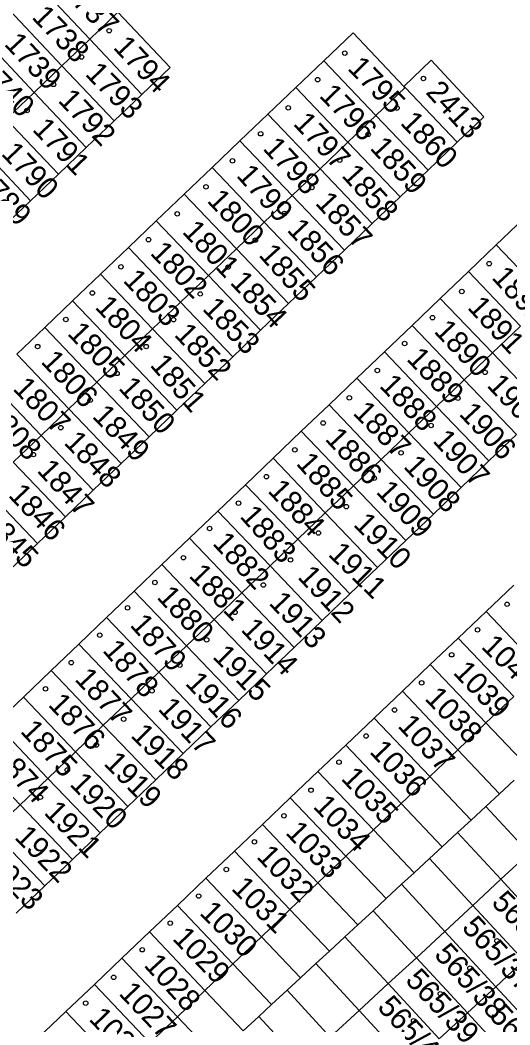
# Model space of a CAD drawing. Extents: x -735249 to -729401, y -1124843 to -1121828.
# Drawn here: x -733357.4 to -733319, y -1123266.5 to -1123187.9 of the extents above; entities that cross this region are included whole.
import ezdxf

# ---------------------------------------------------------------- set-up
doc = ezdxf.new("R2010")
doc.units = 0
for name, color, linetype in [('Vrstva 1', 7, 'Continuous'), ('Vrstva 19', 7, 'Continuous'), ('Vrstva 25', 7, 'Continuous'), ('Vrstva 4', 7, 'Continuous')]:
    doc.layers.add(name, color=color, linetype=linetype)

msp = doc.modelspace()

# ---------------------------------------------------------------- linework, layer by layer
at = {"layer": 'Vrstva 1'}
for points in [[(-733355.97, -1123185.04), (-733351.91, -1123189.36)], [(-733358.16, -1123187.12), (-733354.09, -1123191.44)], [(-733351.91, -1123189.36), (-733349.7, -1123187.25)], [(-733345.62, -1123191.57), (-733349.7, -1123187.25)], [(-733360.34, -1123189.21), (-733356.27, -1123193.53)], [(-733354.09, -1123191.44), (-733351.91, -1123189.36)], [(-733351.91, -1123189.36), (-733347.83, -1123193.68)], [(-733333.59, -1123191.06), (-733331.3, -1123188.87)], [(-733331.3, -1123188.87), (-733327.31, -1123193.05)], [(-733335.78, -1123193.15), (-733333.59, -1123191.06)], [(-733333.59, -1123191.06), (-733329.51, -1123195.34)], [(-733327.31, -1123193.05), (-733325.18, -1123191.01)], [(-733325.18, -1123191.01), (-733321.06, -1123195.43)], [(-733356.27, -1123193.53), (-733354.09, -1123191.44)], [(-733354.09, -1123191.44), (-733350.01, -1123195.76)], [(-733347.83, -1123193.68), (-733345.62, -1123191.57)], [(-733337.96, -1123195.23), (-733335.78, -1123193.15)], [(-733335.78, -1123193.15), (-733331.7, -1123197.43)], [(-733329.51, -1123195.34), (-733327.22, -1123193.15)], [(-733327.31, -1123193.05), (-733327.22, -1123193.15)], [(-733327.22, -1123193.15), (-733323.14, -1123197.42)], [(-733358.45, -1123195.61), (-733356.27, -1123193.53)], [(-733356.27, -1123193.53), (-733352.19, -1123197.84)], [(-733350.01, -1123195.76), (-733347.83, -1123193.68)], [(-733358.45, -1123195.61), (-733354.37, -1123199.92)], [(-733352.19, -1123197.84), (-733350.01, -1123195.76)], [(-733340.15, -1123197.32), (-733337.96, -1123195.23)], [(-733337.96, -1123195.23), (-733333.88, -1123199.51)], [(-733331.7, -1123197.43), (-733329.51, -1123195.34)], [(-733329.51, -1123195.34), (-733325.43, -1123199.61)], [(-733321.06, -1123195.43), (-733323.14, -1123197.42)], [(-733342.33, -1123199.4), (-733340.15, -1123197.32)], [(-733340.15, -1123197.32), (-733336.07, -1123201.6)], [(-733333.88, -1123199.51), (-733331.7, -1123197.43)], [(-733331.7, -1123197.43), (-733327.62, -1123201.7)], [(-733325.43, -1123199.61), (-733323.14, -1123197.42)], [(-733360.62, -1123197.69), (-733356.54, -1123202)], [(-733354.37, -1123199.92), (-733352.19, -1123197.84)], [(-733344.51, -1123201.49), (-733342.33, -1123199.4)], [(-733342.33, -1123199.4), (-733338.25, -1123203.68)], [(-733336.07, -1123201.6), (-733333.88, -1123199.51)], [(-733333.88, -1123199.51), (-733329.8, -1123203.78)], [(-733327.62, -1123201.7), (-733325.43, -1123199.61)], [(-733356.54, -1123202), (-733354.37, -1123199.92)], [(-733358.73, -1123204.09), (-733356.54, -1123202)], [(-733346.7, -1123203.57), (-733344.51, -1123201.49)], [(-733344.51, -1123201.49), (-733340.43, -1123205.77)], [(-733338.25, -1123203.68), (-733336.07, -1123201.6)], [(-733336.07, -1123201.6), (-733331.98, -1123205.87)], [(-733329.8, -1123203.78), (-733327.62, -1123201.7)], [(-733348.88, -1123205.66), (-733346.7, -1123203.57)], [(-733346.7, -1123203.57), (-733342.62, -1123207.85)], [(-733340.43, -1123205.77), (-733338.25, -1123203.68)], [(-733338.25, -1123203.68), (-733334.17, -1123207.95)], [(-733320.09, -1123205.46), (-733317.93, -1123203.39)], [(-733331.98, -1123205.87), (-733329.8, -1123203.78)], [(-733351.07, -1123207.75), (-733348.88, -1123205.66)], [(-733348.88, -1123205.66), (-733344.8, -1123209.94)], [(-733342.62, -1123207.85), (-733340.43, -1123205.77)], [(-733340.43, -1123205.77), (-733336.35, -1123210.04)], [(-733334.17, -1123207.95), (-733331.98, -1123205.87)], [(-733322.26, -1123207.53), (-733320.09, -1123205.46)], [(-733320.09, -1123205.46), (-733316.01, -1123209.73)], [(-733324.47, -1123209.64), (-733322.26, -1123207.53)], [(-733322.26, -1123207.53), (-733318.18, -1123211.8)], [(-733353.25, -1123209.83), (-733351.07, -1123207.75)], [(-733351.07, -1123207.75), (-733346.99, -1123212.03)], [(-733344.8, -1123209.94), (-733342.62, -1123207.85)], [(-733342.62, -1123207.85), (-733338.54, -1123212.13)], [(-733336.35, -1123210.04), (-733334.17, -1123207.95)], [(-733355.44, -1123211.92), (-733353.25, -1123209.83)], [(-733353.25, -1123209.83), (-733349.17, -1123214.11)], [(-733346.99, -1123212.03), (-733344.8, -1123209.94)], [(-733344.8, -1123209.94), (-733340.72, -1123214.21)], [(-733326.67, -1123211.75), (-733324.47, -1123209.64)], [(-733324.47, -1123209.64), (-733320.38, -1123213.91)], [(-733338.54, -1123212.13), (-733336.35, -1123210.04)], [(-733357.62, -1123214), (-733355.44, -1123211.92)], [(-733355.44, -1123211.92), (-733351.36, -1123216.2)], [(-733349.17, -1123214.11), (-733346.99, -1123212.03)], [(-733346.99, -1123212.03), (-733342.9, -1123216.3)], [(-733340.72, -1123214.21), (-733338.54, -1123212.13)], [(-733328.84, -1123213.82), (-733326.67, -1123211.75)], [(-733326.67, -1123211.75), (-733322.59, -1123216.02)], [(-733320.38, -1123213.91), (-733318.18, -1123211.8)], [(-733331.01, -1123215.89), (-733328.84, -1123213.82)], [(-733328.84, -1123213.82), (-733324.76, -1123218.09)], [(-733322.59, -1123216.02), (-733320.38, -1123213.91)], [(-733320.38, -1123213.91), (-733316.3, -1123218.18)], [(-733357.62, -1123214), (-733353.54, -1123218.28)], [(-733351.36, -1123216.2), (-733349.17, -1123214.11)], [(-733349.17, -1123214.11), (-733345.09, -1123218.38)], [(-733342.9, -1123216.3), (-733340.72, -1123214.21)], [(-733359.8, -1123216.09), (-733355.72, -1123220.37)], [(-733353.54, -1123218.28), (-733351.36, -1123216.2)], [(-733351.36, -1123216.2), (-733347.27, -1123220.47)], [(-733345.09, -1123218.38), (-733342.9, -1123216.3)], [(-733333.18, -1123217.96), (-733331.01, -1123215.89)], [(-733331.01, -1123215.89), (-733326.92, -1123220.17)], [(-733324.76, -1123218.09), (-733322.59, -1123216.02)], [(-733322.59, -1123216.02), (-733318.5, -1123220.29)], [(-733355.72, -1123220.37), (-733353.54, -1123218.28)], [(-733353.54, -1123218.28), (-733349.46, -1123222.56)], [(-733347.27, -1123220.47), (-733345.09, -1123218.38)], [(-733335.35, -1123220.04), (-733333.18, -1123217.96)], [(-733333.18, -1123217.96), (-733329.09, -1123222.24)], [(-733326.92, -1123220.17), (-733324.76, -1123218.09)], [(-733324.76, -1123218.09), (-733320.67, -1123222.36)], [(-733337.55, -1123222.14), (-733335.35, -1123220.04)], [(-733335.35, -1123220.04), (-733331.26, -1123224.31)], [(-733329.09, -1123222.24), (-733326.92, -1123220.17)], [(-733326.92, -1123220.17), (-733322.84, -1123224.43)], [(-733357.91, -1123222.45), (-733355.72, -1123220.37)], [(-733355.72, -1123220.37), (-733351.64, -1123224.64)], [(-733349.46, -1123222.56), (-733347.27, -1123220.47)], [(-733320.67, -1123222.36), (-733318.5, -1123220.29)], [(-733357.91, -1123222.45), (-733353.82, -1123226.73)], [(-733351.64, -1123224.64), (-733349.46, -1123222.56)], [(-733339.72, -1123224.22), (-733337.55, -1123222.14)], [(-733337.55, -1123222.14), (-733333.47, -1123226.42)], [(-733331.26, -1123224.31), (-733329.09, -1123222.24)], [(-733329.09, -1123222.24), (-733325, -1123226.51)], [(-733322.84, -1123224.43), (-733320.67, -1123222.36)], [(-733360.09, -1123224.54), (-733356.01, -1123228.81)], [(-733353.82, -1123226.73), (-733351.64, -1123224.64)], [(-733341.89, -1123226.29), (-733339.72, -1123224.22)], [(-733339.72, -1123224.22), (-733335.63, -1123228.49)], [(-733333.47, -1123226.42), (-733331.26, -1123224.31)], [(-733331.26, -1123224.31), (-733327.17, -1123228.58)], [(-733325, -1123226.51), (-733322.84, -1123224.43)], [(-733344.1, -1123228.4), (-733341.89, -1123226.29)], [(-733341.89, -1123226.29), (-733337.8, -1123230.57)], [(-733335.63, -1123228.49), (-733333.47, -1123226.42)], [(-733333.47, -1123226.42), (-733329.38, -1123230.69)], [(-733327.17, -1123228.58), (-733325, -1123226.51)], [(-733356.01, -1123228.81), (-733353.82, -1123226.73)], [(-733358.19, -1123230.9), (-733356.01, -1123228.81)], [(-733346.26, -1123230.47), (-733344.1, -1123228.4)], [(-733344.1, -1123228.4), (-733340.01, -1123232.67)], [(-733337.8, -1123230.57), (-733335.63, -1123228.49)], [(-733335.63, -1123228.49), (-733331.54, -1123232.76)], [(-733329.38, -1123230.69), (-733327.17, -1123228.58)], [(-733348.43, -1123232.54), (-733346.26, -1123230.47)], [(-733346.26, -1123230.47), (-733342.18, -1123234.75)], [(-733340.01, -1123232.67), (-733337.8, -1123230.57)], [(-733337.8, -1123230.57), (-733333.71, -1123234.84)], [(-733331.54, -1123232.76), (-733329.38, -1123230.69)], [(-733350.6, -1123234.61), (-733348.43, -1123232.54)], [(-733348.43, -1123232.54), (-733344.34, -1123236.82)], [(-733342.18, -1123234.75), (-733340.01, -1123232.67)], [(-733340.01, -1123232.67), (-733335.92, -1123236.95)], [(-733333.71, -1123234.84), (-733331.54, -1123232.76)], [(-733320.89, -1123234.14), (-733318.72, -1123232.07)], [(-733323.07, -1123236.21), (-733320.89, -1123234.14)], [(-733320.89, -1123234.14), (-733316.55, -1123238.71)], [(-733352.77, -1123236.69), (-733350.6, -1123234.61)], [(-733350.6, -1123234.61), (-733346.51, -1123238.89)], [(-733344.34, -1123236.82), (-733342.18, -1123234.75)], [(-733342.18, -1123234.75), (-733338.08, -1123239.02)], [(-733335.92, -1123236.95), (-733333.71, -1123234.84)], [(-733354.94, -1123238.76), (-733352.77, -1123236.69)], [(-733352.77, -1123236.69), (-733348.68, -1123240.97)], [(-733325.25, -1123238.28), (-733323.07, -1123236.21)], [(-733323.07, -1123236.21), (-733318.72, -1123240.78)], [(-733346.51, -1123238.89), (-733344.34, -1123236.82)], [(-733344.34, -1123236.82), (-733340.25, -1123241.09)], [(-733338.08, -1123239.02), (-733335.92, -1123236.95)], [(-733327.44, -1123240.37), (-733325.25, -1123238.28)], [(-733325.25, -1123238.28), (-733320.9, -1123242.85)], [(-733357.11, -1123240.83), (-733354.94, -1123238.76)], [(-733354.94, -1123238.76), (-733350.85, -1123243.04)], [(-733348.68, -1123240.97), (-733346.51, -1123238.89)], [(-733346.51, -1123238.89), (-733342.42, -1123243.17)], [(-733340.25, -1123241.09), (-733338.08, -1123239.02)], [(-733329.65, -1123242.47), (-733327.44, -1123240.37)], [(-733327.44, -1123240.37), (-733323.1, -1123244.95)], [(-733359.28, -1123242.91), (-733357.11, -1123240.83)], [(-733357.11, -1123240.83), (-733353.02, -1123245.11)], [(-733350.85, -1123243.04), (-733348.68, -1123240.97)], [(-733348.68, -1123240.97), (-733344.59, -1123245.24)], [(-733342.42, -1123243.17), (-733340.25, -1123241.09)], [(-733359.28, -1123242.91), (-733355.18, -1123247.19)], [(-733331.87, -1123244.59), (-733329.65, -1123242.47)], [(-733329.65, -1123242.47), (-733325.3, -1123247.04)], [(-733320.9, -1123242.85), (-733317.6, -1123246.32)], [(-733353.02, -1123245.11), (-733350.85, -1123243.04)], [(-733350.85, -1123243.04), (-733346.75, -1123247.31)], [(-733344.59, -1123245.24), (-733342.42, -1123243.17)], [(-733334.05, -1123246.66), (-733331.87, -1123244.59)], [(-733331.87, -1123244.59), (-733327.53, -1123249.16)], [(-733361.45, -1123244.98), (-733357.35, -1123249.26)], [(-733355.18, -1123247.19), (-733353.02, -1123245.11)], [(-733353.02, -1123245.11), (-733348.92, -1123249.39)], [(-733346.75, -1123247.31), (-733344.59, -1123245.24)], [(-733323.1, -1123244.95), (-733319.84, -1123248.39)], [(-733336.21, -1123248.71), (-733334.05, -1123246.66)], [(-733334.05, -1123246.66), (-733329.7, -1123251.23)], [(-733357.35, -1123249.26), (-733355.18, -1123247.19)], [(-733355.18, -1123247.19), (-733351.09, -1123251.46)], [(-733348.92, -1123249.39), (-733346.75, -1123247.31)], [(-733325.3, -1123247.04), (-733322.06, -1123250.45)], [(-733319.84, -1123248.39), (-733318.69, -1123247.33)], [(-733320.91, -1123249.38), (-733319.84, -1123248.39)], [(-733359.52, -1123251.33), (-733357.35, -1123249.26)], [(-733357.35, -1123249.26), (-733353.26, -1123253.54)], [(-733338.4, -1123250.8), (-733336.21, -1123248.71)], [(-733336.21, -1123248.71), (-733331.86, -1123253.29)], [(-733327.53, -1123249.16), (-733324.32, -1123252.54)], [(-733351.09, -1123251.46), (-733348.92, -1123249.39)], [(-733322.06, -1123250.45), (-733320.91, -1123249.38)], [(-733317.51, -1123253.05), (-733320.91, -1123249.38)], [(-733340.59, -1123252.89), (-733338.4, -1123250.8)], [(-733338.4, -1123250.8), (-733334.05, -1123255.37)], [(-733323.11, -1123251.42), (-733322.06, -1123250.45)], [(-733359.52, -1123251.33), (-733355.43, -1123255.61)], [(-733353.26, -1123253.54), (-733351.09, -1123251.46)], [(-733329.7, -1123251.23), (-733326.52, -1123254.57)], [(-733324.32, -1123252.54), (-733323.11, -1123251.42)], [(-733319.72, -1123255.09), (-733323.11, -1123251.42)], [(-733342.82, -1123255.01), (-733340.59, -1123252.89)], [(-733340.59, -1123252.89), (-733336.24, -1123257.46)], [(-733325.31, -1123253.46), (-733324.32, -1123252.54)], [(-733355.43, -1123255.61), (-733353.26, -1123253.54)], [(-733331.86, -1123253.29), (-733328.71, -1123256.6)], [(-733326.52, -1123254.57), (-733325.31, -1123253.46)], [(-733321.92, -1123257.13), (-733325.31, -1123253.46)], [(-733327.51, -1123255.48), (-733326.52, -1123254.57)], [(-733345.05, -1123257.13), (-733342.82, -1123255.01)], [(-733342.82, -1123255.01), (-733338.47, -1123259.58)], [(-733334.05, -1123255.37), (-733330.93, -1123258.65)], [(-733328.71, -1123256.6), (-733327.51, -1123255.48)], [(-733324.12, -1123259.16), (-733327.51, -1123255.48)], [(-733319.72, -1123255.09), (-733315.73, -1123259.42)], [(-733357.67, -1123257.75), (-733355.43, -1123255.61)], [(-733347.24, -1123259.21), (-733345.05, -1123257.13)], [(-733345.05, -1123257.13), (-733340.7, -1123261.7)], [(-733329.73, -1123257.55), (-733328.71, -1123256.6)], [(-733321.92, -1123257.13), (-733317.93, -1123261.45)], [(-733336.24, -1123257.46), (-733333.15, -1123260.71)], [(-733330.93, -1123258.65), (-733329.73, -1123257.55)], [(-733326.34, -1123261.22), (-733329.73, -1123257.55)], [(-733331.93, -1123259.58), (-733330.93, -1123258.65)], [(-733349.39, -1123261.26), (-733347.24, -1123259.21)], [(-733347.24, -1123259.21), (-733342.89, -1123263.79)], [(-733324.12, -1123259.16), (-733320.13, -1123263.49)], [(-733338.47, -1123259.58), (-733335.41, -1123262.79)], [(-733333.15, -1123260.71), (-733331.93, -1123259.58)], [(-733328.54, -1123263.25), (-733331.93, -1123259.58)], [(-733334.2, -1123261.67), (-733333.15, -1123260.71)], [(-733351.55, -1123263.32), (-733349.39, -1123261.26)], [(-733349.39, -1123261.26), (-733345.04, -1123265.84)], [(-733340.7, -1123261.7), (-733337.67, -1123264.88)], [(-733335.41, -1123262.79), (-733334.2, -1123261.67)], [(-733330.81, -1123265.35), (-733334.2, -1123261.67)], [(-733326.34, -1123261.22), (-733322.35, -1123265.54)], [(-733320.13, -1123263.49), (-733317.93, -1123261.45)], [(-733353.78, -1123265.44), (-733351.55, -1123263.32)], [(-733351.55, -1123263.32), (-733347.2, -1123267.89)], [(-733336.46, -1123263.77), (-733335.41, -1123262.79)], [(-733328.54, -1123263.25), (-733324.55, -1123267.57)], [(-733342.89, -1123263.79), (-733339.9, -1123266.94)], [(-733337.67, -1123264.88), (-733336.46, -1123263.77)], [(-733333.08, -1123267.45), (-733336.46, -1123263.77)], [(-733322.35, -1123265.54), (-733320.13, -1123263.49)], [(-733320.13, -1123263.49), (-733316.13, -1123267.81)], [(-733338.67, -1123265.81), (-733337.67, -1123264.88)], [(-733356, -1123267.55), (-733353.78, -1123265.44)], [(-733353.78, -1123265.44), (-733349.43, -1123270.02)], [(-733339.9, -1123266.94), (-733338.67, -1123265.81)], [(-733335.28, -1123269.49), (-733338.67, -1123265.81)], [(-733330.81, -1123265.35), (-733326.82, -1123269.68)], [(-733324.55, -1123267.57), (-733322.35, -1123265.54)], [(-733322.35, -1123265.54), (-733318.35, -1123269.87)], [(-733345.04, -1123265.84), (-733342.08, -1123268.96)]]:
    msp.add_lwpolyline(points, dxfattribs=at)
at = {"layer": 'Vrstva 25'}
for centre in [(-733350.39, -1123188.7), (-733331.95, -1123190.45), (-733352.55, -1123190.75), (-733334.07, -1123192.53), (-733325.79, -1123192.44), (-733354.75, -1123192.9), (-733356.82, -1123194.94), (-733336.37, -1123194.73), (-733327.86, -1123194.74), (-733338.53, -1123196.76), (-733330.11, -1123196.81), (-733340.74, -1123198.88), (-733332.34, -1123198.83), (-733342.81, -1123200.91), (-733334.52, -1123200.97), (-733345.06, -1123203.03), (-733336.66, -1123203), (-733347.31, -1123205.05), (-733338.95, -1123205.09), (-733320.64, -1123206.92), (-733349.47, -1123207.17), (-733341.08, -1123207.19), (-733351.71, -1123209.22), (-733343.26, -1123209.29), (-733322.78, -1123209.1), (-733353.78, -1123211.29), (-733345.35, -1123211.31), (-733325.08, -1123211.15), (-733327.26, -1123213.17), (-733355.99, -1123213.41), (-733347.49, -1123213.41), (-733349.78, -1123215.51), (-733329.4, -1123215.28), (-733320.96, -1123215.43), (-733351.88, -1123217.61), (-733331.59, -1123217.42), (-733323.09, -1123217.45), (-733333.64, -1123219.39), (-733325.19, -1123219.58), (-733354.18, -1123219.75), (-733356.32, -1123221.86), (-733335.86, -1123221.49), (-733327.54, -1123221.72), (-733338.08, -1123223.59), (-733329.64, -1123223.71), (-733340.27, -1123225.66), (-733331.82, -1123225.93), (-733342.53, -1123227.64), (-733334.01, -1123227.99), (-733344.58, -1123229.93), (-733336.19, -1123230.1), (-733346.81, -1123231.87), (-733338.32, -1123232.06), (-733319.24, -1123233.57), (-733348.95, -1123233.85), (-733340.54, -1123234.2), (-733351.13, -1123235.99), (-733321.55, -1123235.57), (-733342.76, -1123236.35), (-733323.58, -1123237.52), (-733353.36, -1123238.14), (-733344.86, -1123238.33), (-733325.93, -1123239.72), (-733355.37, -1123240.19), (-733347.04, -1123240.34), (-733328.05, -1123241.84), (-733349.26, -1123242.56), (-733330.28, -1123243.88), (-733351.4, -1123244.58), (-733332.4, -1123245.92), (-733353.67, -1123246.53), (-733355.77, -1123248.67), (-733334.59, -1123248.12), (-733336.71, -1123250.12), (-733339.02, -1123252.16), (-733341.22, -1123254.32), (-733343.38, -1123256.4), (-733345.61, -1123258.52), (-733320.03, -1123259.9), (-733347.8, -1123260.6), (-733322.14, -1123262.04), (-733350.04, -1123262.76), (-733324.47, -1123264.04), (-733352.23, -1123264.78), (-733326.56, -1123266.16)]:
    msp.add_circle(centre, 0.175, dxfattribs=at)
at = {"layer": 'Vrstva 4'}
for points in [[(-733320.9, -1123242.85), (-733318.72, -1123240.78)], [(-733323.1, -1123244.95), (-733320.9, -1123242.85)], [(-733325.3, -1123247.04), (-733323.1, -1123244.95)], [(-733327.53, -1123249.16), (-733325.3, -1123247.04)], [(-733329.7, -1123251.23), (-733327.53, -1123249.16)], [(-733331.86, -1123253.29), (-733329.7, -1123251.23)], [(-733319.72, -1123255.09), (-733317.51, -1123253.05)], [(-733334.05, -1123255.37), (-733331.86, -1123253.29)], [(-733336.24, -1123257.46), (-733334.05, -1123255.37)], [(-733321.92, -1123257.13), (-733319.72, -1123255.09)], [(-733324.12, -1123259.16), (-733321.92, -1123257.13)], [(-733338.47, -1123259.58), (-733336.24, -1123257.46)], [(-733326.34, -1123261.22), (-733324.12, -1123259.16)], [(-733340.7, -1123261.7), (-733338.47, -1123259.58)], [(-733342.89, -1123263.79), (-733340.7, -1123261.7)], [(-733328.54, -1123263.25), (-733326.34, -1123261.22)], [(-733330.81, -1123265.35), (-733328.54, -1123263.25)], [(-733345.04, -1123265.84), (-733342.89, -1123263.79)], [(-733333.08, -1123267.45), (-733330.81, -1123265.35)], [(-733347.2, -1123267.89), (-733345.04, -1123265.84)]]:
    msp.add_lwpolyline(points, dxfattribs=at)

# ---------------------------------------------------------------- texts
at = {"layer": 'Vrstva 19'}
for s, rotation, p in [('1737', 314.6025, (-733354.238, -1123185.631)), ('1738', 313.80249, (-733356.518, -1123187.685)), ('1739', 313.00249, (-733358.668, -1123189.789)), ('1794', 313.20249, (-733350.148, -1123190.048)), ('1740', 314.3025, (-733360.818, -1123191.983)), ('1795', 314.2025, (-733331.798, -1123191.693)), ('1793', 314.4025, (-733352.348, -1123192.142)), ('2413', 312.60249, (-733325.678, -1123193.561)), ('1792', 314.0025, (-733354.468, -1123194.214)), ('1796', 314.1025, (-733334.018, -1123193.834)), ('1791', 313.70249, (-733356.468, -1123196.476)), ('1797', 313.20249, (-733336.058, -1123196.018)), ('1860', 313.60249, (-733327.668, -1123195.966)), ('1798', 312.90249, (-733338.428, -1123197.96)), ('1859', 312.60249, (-733330.038, -1123197.921)), ('1790', 313.50249, (-733358.908, -1123198.367)), ('1789', 313.50249, (-733361.038, -1123200.437)), ('1799', 311.90248, (-733340.498, -1123200.065)), ('1858', 312.30248, (-733332.258, -1123200.063)), ('1800', 313.50249, (-733342.798, -1123202.047)), ('1857', 312.80249, (-733334.328, -1123202.23)), ('1801', 313.30249, (-733344.738, -1123204.478)), ('1856', 313.40249, (-733336.538, -1123204.337)), ('1802', 313.9025, (-733347.258, -1123206.145)), ('1855', 312.00248, (-733338.748, -1123206.284)), ('1803', 313.10249, (-733349.368, -1123208.289)), ('1854', 313.30249, (-733340.998, -1123208.448)), ('1892', 312.40248, (-733320.508, -1123208.052)), ('1804', 313.30249, (-733351.568, -1123210.368)), ('1853', 313.70249, (-733343.158, -1123210.506)), ('1891', 312.80249, (-733322.408, -1123210.4)), ('1890', 313.40249, (-733325.038, -1123212.257)), ('1805', 313.50249, (-733353.728, -1123212.437)), ('1852', 313.50249, (-733345.368, -1123212.527)), ('1806', 313.00249, (-733355.798, -1123214.639)), ('1889', 313.70249, (-733327.178, -1123214.436)), ('1851', 311.20248, (-733347.258, -1123214.888)), ('1807', 313.9025, (-733357.998, -1123216.755)), ('1850', 312.60249, (-733349.728, -1123216.701)), ('1888', 313.70249, (-733329.308, -1123216.526)), ('1905', 313.10249, (-733320.888, -1123216.499)), ('1887', 314.4025, (-733331.378, -1123218.662)), ('1808', 313.70249, (-733360.258, -1123218.786)), ('1849', 313.9025, (-733351.788, -1123218.915)), ('1906', 313.10249, (-733323.068, -1123218.719)), ('1848', 313.9025, (-733354.008, -1123220.975)), ('1886', 313.20249, (-733333.558, -1123220.688)), ('1907', 312.40248, (-733325.128, -1123220.822)), ('1847', 312.80249, (-733356.108, -1123223.16)), ('1885', 311.80248, (-733335.818, -1123222.595)), ('1908', 312.90249, (-733327.418, -1123222.84)), ('1884', 313.20249, (-733338.048, -1123224.738)), ('1909', 312.80249, (-733329.568, -1123224.82)), ('1846', 313.40249, (-733358.358, -1123225.087)), ('1845', 313.80249, (-733360.488, -1123227.225)), ('1883', 311.70248, (-733340.228, -1123226.726)), ('1910', 314.6025, (-733331.338, -1123227.391)), ('1882', 312.90249, (-733342.368, -1123228.85)), ('1911', 315.80251, (-733333.318, -1123229.727)), ('1881', 314.8025, (-733344.228, -1123231.39)), ('1912', 313.10249, (-733335.708, -1123231.479)), ('1880', 312.90249, (-733346.728, -1123233.06)), ('1913', 313.60249, (-733337.958, -1123233.526)), ('1879', 312.10248, (-733348.828, -1123235.234)), ('1914', 313.20249, (-733340.148, -1123235.598)), ('1878', 311.20248, (-733350.968, -1123237.218)), ('1040', 315.50251, (-733321.338, -1123236.958)), ('1915', 314.8025, (-733342.368, -1123237.73)), ('1039', 313.70249, (-733323.538, -1123238.966)), ('1877', 313.10249, (-733353.158, -1123239.479)), ('1916', 313.10249, (-733344.508, -1123239.799)), ('1876', 313.50249, (-733355.238, -1123241.477)), ('1038', 314.3025, (-733325.758, -1123241.003)), ('1917', 313.30249, (-733346.638, -1123241.808)), ('1875', 313.10249, (-733357.418, -1123243.549)), ('1037', 313.10249, (-733327.878, -1123243.129)), ('1918', 315.00251, (-733348.778, -1123243.9)), ('1036', 314.1025, (-733330.078, -1123245.164)), ('1874', 313.20249, (-733359.648, -1123245.608)), ('1919', 314.8025, (-733350.888, -1123246.09)), ('1920', 314.2025, (-733353.548, -1123247.703)), ('1035', 313.30249, (-733332.308, -1123247.248)), ('1921', 314.2025, (-733355.568, -1123249.923)), ('1034', 313.80249, (-733334.498, -1123249.445)), ('1033', 313.40249, (-733336.658, -1123251.487)), ('1922', 314.4025, (-733357.868, -1123251.862)), ('1923', 314.1025, (-733360.128, -1123254.004)), ('1032', 313.80249, (-733338.928, -1123253.365)), ('1031', 315.00251, (-733340.898, -1123255.87)), ('565/36', 313.80249, (-733320.538, -1123256.975)), ('1030', 315.40251, (-733343.398, -1123257.789)), ('565/37', 312.50249, (-733322.858, -1123258.912)), ('1029', 314.2025, (-733345.508, -1123259.783)), ('565/38', 312.10248, (-733325.018, -1123261.034)), ('1028', 312.50249, (-733347.748, -1123261.842)), ('565/39', 313.30249, (-733327.278, -1123263.048)), ('1027', 313.60249, (-733349.708, -1123264.066)), ('565/40', 312.60249, (-733329.468, -1123265.141)), ('565/11', 312.10248, (-733320.708, -1123265.814)), ('1026', 314.4025, (-733352.058, -1123266.072))]:
    msp.add_text(s, height=1.7, rotation=rotation, dxfattribs=at).set_placement(p)

doc.saveas('drawing.dxf')
